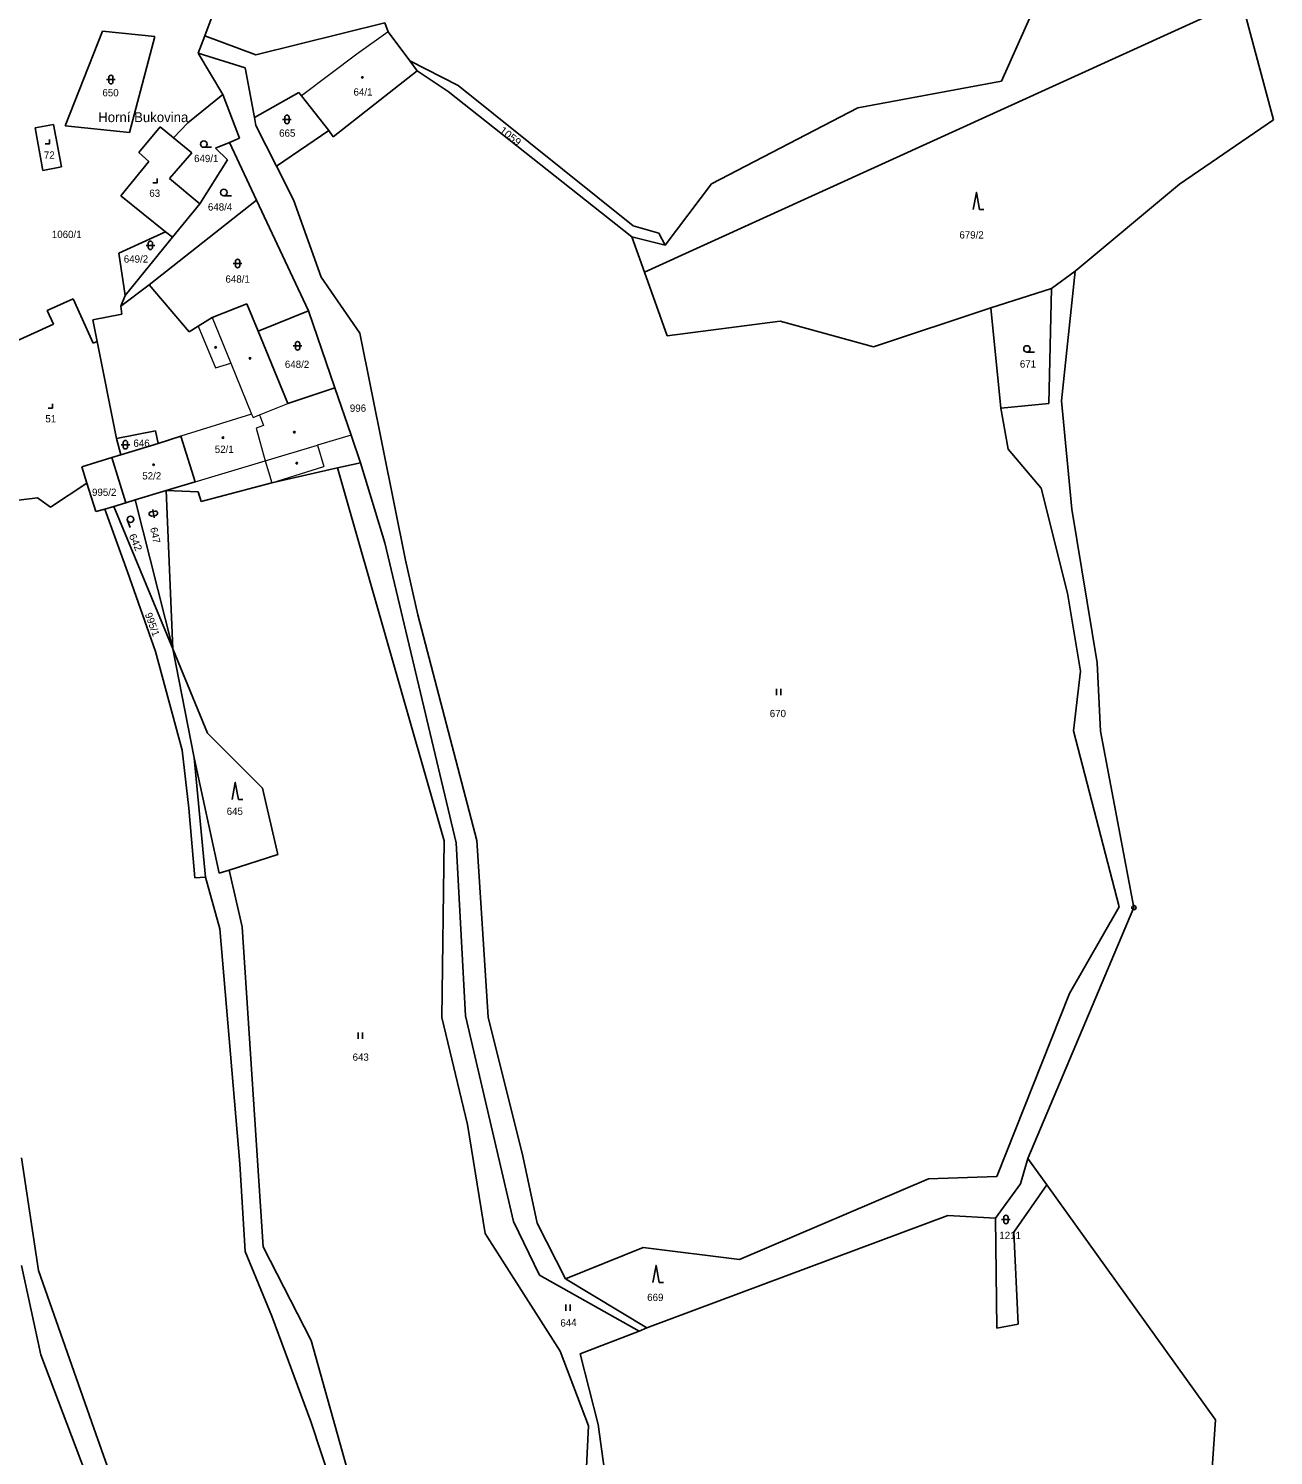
# Model space of a CAD drawing. Extents: x -744132 to -742433, y -984679 to -982287.
# Drawn here: x -742836 to -742545.3, y -983197.5 to -982864.5 of the extents above; entities that cross this region are included whole.
import ezdxf
from ezdxf.enums import TextEntityAlignment as Align

# ---------------------------------------------------------------- set-up
doc = ezdxf.new("R2010")
doc.units = 0
doc.header["$LTSCALE"] = 0.68
for name, color, linetype, lineweight in [('1', 7, 'Continuous', 25), ('3', 7, 'Continuous', 25), ('4', 7, 'Continuous', 13), ('5', 7, 'Continuous', 25), ('7', 7, 'Continuous', 13), ('8', 7, 'Continuous', 25)]:
    doc.layers.add(name, color=color, linetype=linetype, lineweight=lineweight)
doc.layers.add('2', color=7, linetype='Continuous')

msp = doc.modelspace()

# ---------------------------------------------------------------- linework, layer by layer
at = {"layer": '1'}
for p, q in [((-742587.81, -982829.47), (-742608.79, -982876.79)), ((-742791.71, -982857.81), (-742794.83, -982866.22)), ((-742692.17, -982921.38), (-742552.79, -982857.93)), ((-742545.32, -982885.8), (-742552.79, -982857.93)), ((-742752.77, -982863.2), (-742782.93, -982870.65)), ((-742752.77, -982863.2), (-742752.05, -982865.3)), ((-742818.69, -982865.1), (-742827.41, -982887.24)), ((-742806.51, -982866.34), (-742818.69, -982865.1)), ((-742812.41, -982888.76), (-742806.51, -982866.34)), ((-742794.83, -982866.22), (-742796.34, -982870.28)), ((-742794.83, -982866.22), (-742782.93, -982870.65)), ((-742746.97, -982872.06), (-742752.05, -982865.3)), ((-742785.41, -982873.69), (-742796.34, -982870.28)), ((-742796.34, -982870.28), (-742790.61, -982879.87)), ((-742746.97, -982872.06), (-742735.65, -982877.77)), ((-742746.97, -982872.06), (-742745.27, -982874.34)), ((-742783.25, -982885.29), (-742785.41, -982873.69)), ((-742764.83, -982889.76), (-742745.27, -982874.34)), ((-742745.27, -982874.34), (-742738.04, -982879.16)), ((-742798.8, -982886.54), (-742790.61, -982879.87)), ((-742790.61, -982879.87), (-742786.72, -982890.06)), ((-742772.86, -982879.46), (-742783.25, -982885.29)), ((-742772.26, -982880.23), (-742772.86, -982879.46)), ((-742738.04, -982879.16), (-742695.13, -982913.12)), ((-742735.65, -982877.77), (-742694.8, -982910.55)), ((-742608.79, -982876.79), (-742642.35, -982882.98)), ((-742765.89, -982888.32), (-742772.26, -982880.23)), ((-742642.35, -982882.98), (-742676.54, -982900.74)), ((-742802.16, -982889.97), (-742798.8, -982886.54)), ((-742782.9, -982887.16), (-742783.25, -982885.29)), ((-742567.28, -982900.85), (-742545.32, -982885.8)), ((-742834.42, -982887.7), (-742830.12, -982886.92)), ((-742834.42, -982887.7), (-742832.62, -982897.62)), ((-742830.12, -982886.92), (-742828.25, -982896.76)), ((-742827.41, -982887.24), (-742812.41, -982888.76)), ((-742810.23, -982893.42), (-742805.21, -982887.46)), ((-742805.21, -982887.46), (-742802.16, -982889.97)), ((-742778.08, -982896.63), (-742782.9, -982887.16)), ((-742778.08, -982896.63), (-742765.89, -982888.32)), ((-742765.89, -982888.32), (-742764.83, -982889.76)), ((-742802.16, -982889.97), (-742797.89, -982893.5)), ((-742792.32, -982892.43), (-742789.08, -982891.09)), ((-742789.55, -982895.12), (-742792.32, -982892.43)), ((-742786.72, -982890.06), (-742789.08, -982891.09)), ((-742789.08, -982891.09), (-742782.77, -982904.52)), ((-742814.4, -982903.56), (-742807.88, -982895.51)), ((-742807.88, -982895.51), (-742810.23, -982893.42)), ((-742797.89, -982893.5), (-742803.1, -982899.48)), ((-742795.95, -982905.4), (-742789.55, -982895.12)), ((-742832.62, -982897.62), (-742828.25, -982896.76)), ((-742803.1, -982899.48), (-742795.95, -982905.4)), ((-742774.1, -982904.44), (-742778.08, -982896.63)), ((-742676.54, -982900.74), (-742687.37, -982915.09)), ((-742591.64, -982921.13), (-742567.28, -982900.85)), ((-742803.97, -982911.93), (-742814.4, -982903.56)), ((-742807.83, -982924.3), (-742782.77, -982904.52)), ((-742802.4, -982913.15), (-742795.95, -982905.4)), ((-742782.77, -982904.52), (-742770.6, -982930.39)), ((-742767.63, -982922.54), (-742774.1, -982904.44)), ((-742803.97, -982911.93), (-742814.88, -982916.94)), ((-742813.41, -982926.82), (-742802.4, -982913.15)), ((-742802.4, -982913.15), (-742803.97, -982911.93)), ((-742687.37, -982915.09), (-742695.13, -982913.12)), ((-742695.13, -982913.12), (-742692.17, -982921.38)), ((-742694.8, -982910.55), (-742688.79, -982912.28)), ((-742688.79, -982912.28), (-742687.37, -982915.09)), ((-742814.88, -982916.94), (-742813.41, -982926.82)), ((-742758.64, -982935.61), (-742767.63, -982922.54)), ((-742692.17, -982921.38), (-742686.84, -982936.22)), ((-742597.15, -982925.17), (-742591.64, -982921.13)), ((-742807.83, -982924.3), (-742814.41, -982929.31)), ((-742798.47, -982935.26), (-742807.83, -982924.3)), ((-742597.15, -982925.17), (-742611.31, -982929.64)), ((-742597.75, -982952), (-742597.15, -982925.17)), ((-742831.66, -982930.29), (-742825.59, -982927.57)), ((-742825.59, -982927.57), (-742820.86, -982937.96)), ((-742814.41, -982929.31), (-742813.41, -982926.82)), ((-742814.41, -982929.31), (-742814.23, -982931.16)), ((-742793.14, -982931.9), (-742785.02, -982928.71)), ((-742785.02, -982928.71), (-742782.39, -982935.09)), ((-742638.69, -982938.75), (-742611.31, -982929.64)), ((-742611.31, -982929.64), (-742609.01, -982953.08)), ((-742830.15, -982933.45), (-742831.66, -982930.29)), ((-742820.95, -982932.5), (-742814.23, -982931.16)), ((-742820.95, -982932.5), (-742819.95, -982937.52)), ((-742796.39, -982933.95), (-742793.14, -982931.9)), ((-742782.39, -982935.09), (-742770.6, -982930.39)), ((-742770.6, -982930.39), (-742764.45, -982948.37)), ((-742686.84, -982936.22), (-742660.5, -982932.8)), ((-742660.5, -982932.8), (-742638.69, -982938.75)), ((-742841.59, -982938.68), (-742830.15, -982933.45)), ((-742798.47, -982935.26), (-742796.39, -982933.95)), ((-742782.39, -982935.09), (-742775.41, -982951.97)), ((-742747.97, -982988.56), (-742758.64, -982935.61)), ((-742820.86, -982937.96), (-742819.95, -982937.52)), ((-742819.95, -982937.52), (-742815.41, -982960.21)), ((-742775.41, -982951.97), (-742764.45, -982948.37)), ((-742764.45, -982948.37), (-742760.69, -982959.37)), ((-742609.01, -982953.08), (-742597.75, -982952)), ((-742609.01, -982953.08), (-742607.23, -982962.64)), ((-742815.41, -982960.21), (-742806.31, -982958.4)), ((-742806.31, -982958.4), (-742805.73, -982961.3)), ((-742800.4, -982959.65), (-742805.73, -982961.3)), ((-742800.4, -982959.65), (-742797.1, -982970.29)), ((-742760.69, -982959.37), (-742758.48, -982965.85)), ((-742815.41, -982960.21), (-742814.4, -982963.97)), ((-742805.73, -982961.3), (-742814.4, -982963.97)), ((-742607.23, -982962.64), (-742599.53, -982971.76)), ((-742816.56, -982964.64), (-742823.52, -982966.79)), ((-742814.4, -982963.97), (-742816.56, -982964.64)), ((-742816.56, -982964.64), (-742813.28, -982975.18)), ((-742763.88, -982967.04), (-742758.48, -982965.85)), ((-742758.48, -982965.85), (-742752.77, -982984.51)), ((-742823.52, -982966.79), (-742822.35, -982970.57)), ((-742779.17, -982970.5), (-742763.88, -982967.04)), ((-742763.88, -982967.04), (-742738.93, -983054.03)), ((-742822.35, -982970.57), (-742830.88, -982976.2)), ((-742820.27, -982977.22), (-742822.35, -982970.57)), ((-742811.11, -982974.52), (-742803.87, -982972.32)), ((-742803.87, -982972.32), (-742797.1, -982970.29)), ((-742803.87, -982972.32), (-742796.36, -982972.63)), ((-742802.26, -983009.24), (-742803.87, -982972.32)), ((-742796.36, -982972.63), (-742795.66, -982974.87)), ((-742795.66, -982974.87), (-742779.17, -982970.5)), ((-742599.53, -982971.76), (-742593.41, -982996.3)), ((-742845.9, -982975.5), (-742833.9, -982973.99)), ((-742833.9, -982973.99), (-742830.88, -982976.2)), ((-742818.19, -982976.66), (-742816.05, -982976.01)), ((-742816.05, -982976.01), (-742813.28, -982975.18)), ((-742816.05, -982976.01), (-742802.26, -983009.24)), ((-742813.28, -982975.18), (-742811.11, -982974.52)), ((-742811.11, -982974.52), (-742802.26, -983009.24)), ((-742818.19, -982976.66), (-742820.27, -982977.22)), ((-742812.86, -982991.3), (-742818.19, -982976.66)), ((-742586.5, -983012.5), (-742592.42, -982976.69)), ((-742752.77, -982984.51), (-742736.12, -983054.54)), ((-742745.12, -983001.29), (-742747.97, -982988.56)), ((-742806.37, -983009.85), (-742812.86, -982991.3)), ((-742593.41, -982996.3), (-742590.34, -983014.47)), ((-742731.31, -983053.97), (-742745.12, -983001.29)), ((-742797.27, -983034.73), (-742802.26, -983009.24)), ((-742802.26, -983009.24), (-742794.21, -983028.92)), ((-742800.11, -983032.89), (-742806.37, -983009.85)), ((-742585.74, -983028.51), (-742586.5, -983012.5)), ((-742590.34, -983014.47), (-742591.98, -983028.37)), ((-742794.21, -983028.92), (-742781.37, -983041.76)), ((-742591.98, -983028.37), (-742581.33, -983069.51)), ((-742577.91, -983069.64), (-742585.74, -983028.51)), ((-742798.54, -983046.44), (-742800.11, -983032.89)), ((-742797.27, -983034.73), (-742794.7, -983062.52)), ((-742791.46, -983061.63), (-742797.27, -983034.73)), ((-742781.37, -983041.76), (-742777.78, -983057.27)), ((-742798.54, -983046.44), (-742797.16, -983062.68)), ((-742738.93, -983054.03), (-742739.48, -983095.32)), ((-742736.12, -983054.54), (-742733.97, -983094.9)), ((-742728.65, -983095.24), (-742731.31, -983053.97)), ((-742777.78, -983057.27), (-742789.17, -983060.9)), ((-742797.16, -983062.68), (-742794.7, -983062.52)), ((-742794.7, -983062.52), (-742791.29, -983074.61)), ((-742602.68, -983128.17), (-742577.91, -983069.64)), ((-742581.33, -983069.51), (-742592.95, -983089.73)), ((-742791.29, -983074.61), (-742786.63, -983129.47)), ((-742781.18, -983148.82), (-742786.11, -983074.11)), ((-742592.95, -983089.73), (-742609.93, -983132.38)), ((-742739.48, -983095.32), (-742733.46, -983120.28)), ((-742733.97, -983094.9), (-742722.75, -983142.89)), ((-742720.57, -983127.68), (-742728.65, -983095.24)), ((-742733.46, -983120.28), (-742729.39, -983145.7)), ((-742833.69, -983154.35), (-742837.63, -983128.02)), ((-742786.63, -983129.47), (-742785.4, -983149.94)), ((-742717.23, -983143.26), (-742720.57, -983127.68)), ((-742604.38, -983134.08), (-742602.68, -983128.17)), ((-742598.24, -983134.35), (-742602.68, -983128.17)), ((-742625.84, -983132.97), (-742670.02, -983151.81)), ((-742609.93, -983132.38), (-742625.84, -983132.97)), ((-742610.21, -983142.16), (-742604.38, -983134.08)), ((-742605.95, -983145.43), (-742598.24, -983134.35)), ((-742558.82, -983189.2), (-742598.24, -983134.35)), ((-742722.75, -983142.89), (-742716.72, -983155.47)), ((-742691.6, -983167.71), (-742621.36, -983141.51)), ((-742621.36, -983141.51), (-742610.21, -983142.16)), ((-742610.21, -983142.16), (-742609.88, -983167.81)), ((-742729.39, -983145.7), (-742711.83, -983173.17)), ((-742710.65, -983156.3), (-742717.23, -983143.26)), ((-742604.95, -983166.86), (-742605.95, -983145.43)), ((-742770.02, -983170.68), (-742781.18, -983148.82)), ((-742692.45, -983148.97), (-742710.65, -983156.3)), ((-742670.02, -983151.81), (-742692.45, -983148.97)), ((-742785.4, -983149.94), (-742779.19, -983165.04)), ((-742833.08, -983174.04), (-742837.62, -983153.2)), ((-742820.73, -983191.17), (-742833.69, -983154.35)), ((-742716.72, -983155.47), (-742693.42, -983168.48)), ((-742710.65, -983156.3), (-742691.6, -983167.71)), ((-742779.19, -983165.04), (-742770.06, -983189.61)), ((-742693.42, -983168.48), (-742707.15, -983173.8)), ((-742693.42, -983168.48), (-742691.6, -983167.71)), ((-742609.88, -983167.81), (-742604.95, -983166.86)), ((-742761.1, -983202.34), (-742770.02, -983170.68)), ((-742821.79, -983203.81), (-742833.08, -983174.04)), ((-742711.83, -983173.17), (-742705.27, -983190.59)), ((-742707.15, -983173.8), (-742702.97, -983190.25)), ((-742770.06, -983189.61), (-742764.98, -983204.88)), ((-742560.62, -983214.63), (-742558.82, -983189.2)), ((-742797.5, -983256.24), (-742820.73, -983191.17)), ((-742705.27, -983190.59), (-742706.27, -983211.27)), ((-742702.97, -983190.25), (-742699.94, -983212.21))]:
    msp.add_line(p, q, dxfattribs=at)
for points in [[(-742592.42, -982976.69), (-742594.78, -982951.4), (-742591.64, -982921.13)], [(-742786.11, -983074.11), (-742789.17, -983060.9), (-742791.46, -983061.63)]]:
    msp.add_lwpolyline(points, dxfattribs=at)
at = {"layer": '3'}
for p, q in [((-742817.761, -982876.401), (-742815.759, -982876.401)), ((-742817.261, -982875.901), (-742817.261, -982876.902)), ((-742816.259, -982876.902), (-742816.259, -982875.901)), ((-742776.661, -982885.701), (-742774.659, -982885.701)), ((-742776.161, -982885.201), (-742776.161, -982886.202)), ((-742775.159, -982886.202), (-742775.159, -982885.201)), ((-742795.043, -982892.21), (-742793.293, -982892.21)), ((-742790.373, -982903.51), (-742788.623, -982903.51)), ((-742613.94, -982906.75), (-742612.944, -982906.75)), ((-742808.511, -982915.091), (-742806.509, -982915.091)), ((-742808.011, -982914.591), (-742808.011, -982915.592)), ((-742807.009, -982915.592), (-742807.009, -982914.591)), ((-742788.181, -982919.341), (-742786.179, -982919.341)), ((-742787.681, -982918.841), (-742787.681, -982919.842)), ((-742786.679, -982919.842), (-742786.679, -982918.841)), ((-742774.171, -982938.551), (-742772.169, -982938.551)), ((-742773.671, -982938.051), (-742773.671, -982939.052)), ((-742772.669, -982939.052), (-742772.669, -982938.051)), ((-742602.883, -982940.02), (-742601.133, -982940.02)), ((-742814.361, -982961.621), (-742812.359, -982961.621)), ((-742813.861, -982961.121), (-742813.861, -982962.122)), ((-742812.859, -982962.122), (-742812.859, -982961.121)), ((-742812.878, -982979.297), (-742812.279, -982980.941)), ((-742806.407, -982977.121), (-742807.396, -982977.278)), ((-742807.24, -982978.266), (-742806.251, -982978.11)), ((-742806.98, -982976.705), (-742806.667, -982978.683)), ((-742661.371, -983020.11), (-742661.371, -983018.61)), ((-742660.37, -983020.11), (-742660.37, -983018.61)), ((-742786.96, -983044.45), (-742785.964, -983044.45)), ((-742759.011, -983100.29), (-742759.011, -983098.79)), ((-742758.01, -983100.29), (-742758.01, -983098.79)), ((-742608.791, -983142.441), (-742606.789, -983142.441)), ((-742608.291, -983141.941), (-742608.291, -983142.942)), ((-742607.289, -983142.942), (-742607.289, -983141.941)), ((-742688.71, -983157.14), (-742687.714, -983157.14)), ((-742710.501, -983163.75), (-742710.501, -983162.25)), ((-742709.5, -983163.75), (-742709.5, -983162.25))]:
    msp.add_line(p, q, dxfattribs=at)
for points in [[(-742832.111, -982891.42), (-742831.11, -982891.42), (-742831.11, -982890.42)], [(-742806.921, -982900.5), (-742805.92, -982900.5), (-742805.92, -982899.5)], [(-742613.94, -982906.75), (-742614.69, -982902.75), (-742615.44, -982906.75)], [(-742831.421, -982953.07), (-742830.42, -982953.07), (-742830.42, -982952.07)], [(-742786.96, -983044.45), (-742787.71, -983040.45), (-742788.46, -983044.45)], [(-742688.71, -983157.14), (-742689.46, -983153.14), (-742690.21, -983157.14)]]:
    msp.add_lwpolyline(points, dxfattribs=at)
for centre in [(-742795.0429, -982891.4598), (-742790.3729, -982902.7598), (-742602.8829, -982939.2698), (-742812.1726, -982979.0401)]:
    msp.add_circle(centre, 0.75, dxfattribs=at)
for centre, start, end in [((-742816.76, -982875.9009), 0, 180), ((-742816.76, -982876.9009), 180, 359.98789), ((-742775.66, -982885.2009), 0, 180), ((-742775.66, -982886.2009), 180, 359.98789), ((-742807.51, -982914.5909), 0, 180), ((-742807.51, -982915.5909), 180, 359.98789), ((-742787.18, -982918.8409), 0, 180), ((-742787.18, -982919.8409), 180, 359.98789), ((-742773.17, -982938.0509), 0, 180), ((-742773.17, -982939.0509), 180, 359.98789), ((-742813.36, -982961.1209), 0, 180), ((-742813.36, -982962.1209), 180, 359.98789), ((-742807.317, -982977.7719), 99, 278.98789), ((-742806.3294, -982977.6155), 279, 99), ((-742607.79, -983141.9409), 0, 180), ((-742607.79, -983142.9409), 180, 359.98789)]:
    msp.add_arc(centre, 0.5, start, end, dxfattribs=at)
at = {"layer": '4'}
for p, q in [((-742793.14, -982931.9), (-742788.72, -982942.62)), ((-742788.72, -982942.62), (-742783.89, -982954.5)), ((-742782.02, -982954.65), (-742775.41, -982951.97)), ((-742783.89, -982954.5), (-742800.4, -982959.65)), ((-742783.89, -982954.5), (-742783.54, -982955.26)), ((-742783.54, -982955.26), (-742782.02, -982954.65)), ((-742782.02, -982954.65), (-742781.1, -982957.17)), ((-742781.1, -982957.17), (-742782.84, -982957.77)), ((-742782.84, -982957.77), (-742780.71, -982965.37)), ((-742760.69, -982959.37), (-742768.54, -982961.72)), ((-742780.71, -982965.37), (-742768.54, -982961.72)), ((-742768.54, -982961.72), (-742767, -982966.7)), ((-742797.1, -982970.29), (-742780.71, -982965.37)), ((-742780.71, -982965.37), (-742779.17, -982970.5)), ((-742779.17, -982970.5), (-742767, -982966.7))]:
    msp.add_line(p, q, dxfattribs=at)
for points in [[(-742752.05, -982865.3), (-742759.31, -982870.45), (-742772.26, -982880.23)], [(-742796.39, -982933.95), (-742792.35, -982943.68), (-742788.72, -982942.62)]]:
    msp.add_lwpolyline(points, dxfattribs=at)
at = {"layer": '5'}
for centre in [(-742758.0268, -982875.9092), (-742792.3068, -982938.9092), (-742784.2568, -982941.4692), (-742790.5768, -982959.9892), (-742773.9068, -982958.6892), (-742806.7868, -982966.2992), (-742773.3568, -982965.9292)]:
    msp.add_circle(centre, 0.175, dxfattribs=at)
at = {"layer": '8'}
for radius in [0.5, 0.0303]:
    msp.add_circle((-742577.91, -983069.6399), radius, dxfattribs=at)

# ---------------------------------------------------------------- texts
at = {"layer": '2'}
for s, p in [('650', (-742818.73, -982880.305)), ('64/1', (-742760.1, -982880.145)), ('665', (-742777.47, -982889.745)), ('72', (-742832.39, -982894.875)), ('649/1', (-742797.33, -982895.665)), ('63', (-742807.78, -982903.775)), ('648/4', (-742794.1, -982906.975)), ('1060/1', (-742830.54, -982913.385)), ('679/2', (-742618.65, -982913.505)), ('649/2', (-742813.74, -982919.125)), ('648/1', (-742790, -982923.805)), ('648/2', (-742776.13, -982943.705)), ('671', (-742604.53, -982943.625)), ('996', (-742760.96, -982953.935)), ('51', (-742832.05, -982956.405)), ('646', (-742811.49, -982962.115)), ('52/1', (-742792.5, -982963.535)), ('52/2', (-742809.42, -982969.735)), ('995/2', (-742821.16, -982973.565)), ('670', (-742662.93, -983025.205)), ('645', (-742789.72, -983048.015)), ('643', (-742760.32, -983105.395)), ('1211', (-742609.33, -983147.005)), ('669', (-742691.54, -983161.465))]:
    msp.add_text(s, height=1.7, dxfattribs=at).set_placement(p)
at = {"layer": '2', "width": 1.1}
for s, rotation, p in [('1059', 322, (-742726.171, -982888.544)), ('642', 294, (-742812.608, -982982.842))]:
    msp.add_text(s, height=1.7, rotation=rotation, dxfattribs=at).set_placement(p)
at = {"layer": '2'}
for s, rotation, p in [('647', 282, (-742807.605, -982981.088)), ('995/1', 290, (-742808.849, -983001.175)), ('644', 3, (-742711.767, -983167.464))]:
    msp.add_text(s, height=1.7, rotation=rotation, dxfattribs=at).set_placement(p)
at = {"layer": '7'}
msp.add_text('Horní Bukovina', height=2.3, dxfattribs=at).set_placement((-742809.19, -982886.335), align=Align.CENTER)

doc.saveas('drawing.dxf')
